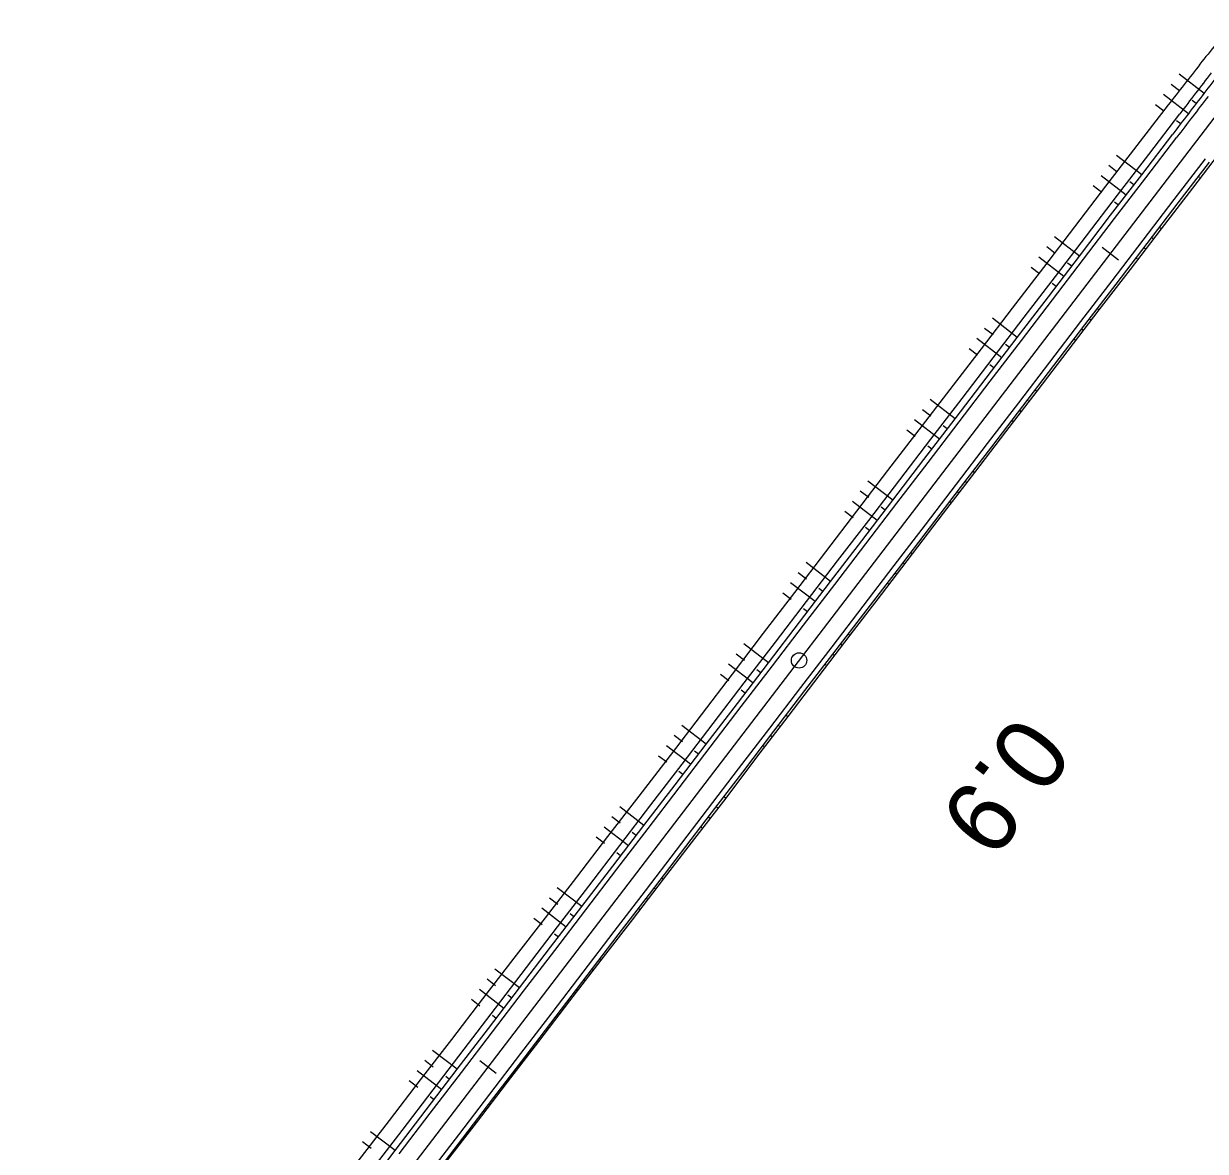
# Model space of a CAD drawing. Extents: x -481645 to -478728, y -1113199 to -1110710.
# Drawn here: x -479367.1 to -479251.7, y -1111179 to -1111068.9 of the extents above; entities that cross this region are included whole.
import ezdxf

# ---------------------------------------------------------------- set-up
doc = ezdxf.new("R2010")
doc.units = 0
for name, color, linetype in [('CP14_HATCH_SLOPE_L', 7, 'Continuous'), ('CP1_HECTOMETRY', 7, 'Continuous'), ('O6_HATCH_SLOPE_L', 7, 'Continuous'), ('O6_HATCH_SLOPE_R', 7, 'Continuous'), ('O6_HLBODY', 7, 'Continuous'), ('O6_HRANA_TELESO', 7, 'Continuous'), ('O6_OSA', 7, 'Continuous'), ('O6_VOZOVKA', 7, 'Continuous'), ('O6_ZPEVKRAJ', 7, 'Continuous')]:
    doc.layers.add(name, color=color, linetype=linetype)

msp = doc.modelspace()

# ---------------------------------------------------------------- linework, layer by layer
at = {"layer": 'CP14_HATCH_SLOPE_L'}
for p, q in [((-479252.35, -1111083.82), (-479252.25, -1111083.89)), ((-479252.15, -1111083.97), (-479252.15, -1111083.97)), ((-479256.15, -1111088.78), (-479255.95, -1111088.93)), ((-479256.91, -1111089.77), (-479256.81, -1111089.85)), ((-479256.71, -1111089.92), (-479256.71, -1111089.92)), ((-479257.67, -1111090.76), (-479257.47, -1111090.91)), ((-479258.43, -1111091.76), (-479258.33, -1111091.83)), ((-479258.23, -1111091.91), (-479258.23, -1111091.91)), ((-479262.23, -1111096.72), (-479262.04, -1111096.86)), ((-479262.99, -1111097.71), (-479262.89, -1111097.78)), ((-479262.8, -1111097.86), (-479262.8, -1111097.86)), ((-479263.75, -1111098.71), (-479263.56, -1111098.85)), ((-479264.51, -1111099.7), (-479264.41, -1111099.77)), ((-479264.32, -1111099.84), (-479264.32, -1111099.84)), ((-479268.3, -1111104.66), (-479268.12, -1111104.8)), ((-479269.07, -1111105.65), (-479268.98, -1111105.72)), ((-479268.89, -1111105.79), (-479268.89, -1111105.79)), ((-479269.83, -1111106.65), (-479269.65, -1111106.78)), ((-479270.58, -1111107.64), (-479270.49, -1111107.71)), ((-479270.41, -1111107.77), (-479270.41, -1111107.77)), ((-479274.38, -1111112.6), (-479274.21, -1111112.73)), ((-479275.14, -1111113.59), (-479275.06, -1111113.66)), ((-479274.97, -1111113.72), (-479274.97, -1111113.72)), ((-479275.9, -1111114.59), (-479275.73, -1111114.72)), ((-479276.66, -1111115.58), (-479276.58, -1111115.64)), ((-479276.49, -1111115.71), (-479276.49, -1111115.71)), ((-479280.46, -1111120.54), (-479280.29, -1111120.67)), ((-479281.22, -1111121.53), (-479281.14, -1111121.6)), ((-479281.05, -1111121.66), (-479281.05, -1111121.66)), ((-479282.74, -1111123.52), (-479282.66, -1111123.58)), ((-479281.98, -1111122.53), (-479281.81, -1111122.66)), ((-479282.57, -1111123.65), (-479282.57, -1111123.65)), ((-479286.54, -1111128.48), (-479286.37, -1111128.61)), ((-479288.06, -1111130.47), (-479287.89, -1111130.6)), ((-479287.3, -1111129.47), (-479287.22, -1111129.54)), ((-479287.13, -1111129.6), (-479287.13, -1111129.6)), ((-479288.82, -1111131.46), (-479288.74, -1111131.52)), ((-479288.65, -1111131.59), (-479288.65, -1111131.59)), ((-479293.38, -1111137.42), (-479293.3, -1111137.48)), ((-479292.62, -1111136.42), (-479292.45, -1111136.55)), ((-479294.14, -1111138.41), (-479293.97, -1111138.53)), ((-479293.21, -1111137.54), (-479293.21, -1111137.54)), ((-479294.9, -1111139.4), (-479294.82, -1111139.46)), ((-479294.73, -1111139.53), (-479294.73, -1111139.53)), ((-479298.7, -1111144.36), (-479298.49, -1111144.52)), ((-479299.46, -1111145.36), (-479299.35, -1111145.43)), ((-479299.25, -1111145.51), (-479299.25, -1111145.51)), ((-479300.22, -1111146.35), (-479300.02, -1111146.5)), ((-479300.98, -1111147.34), (-479300.88, -1111147.42)), ((-479300.78, -1111147.49), (-479300.78, -1111147.49)), ((-479304.78, -1111152.3), (-479304.6, -1111152.44)), ((-479305.54, -1111153.3), (-479305.45, -1111153.36)), ((-479305.36, -1111153.43), (-479305.36, -1111153.43)), ((-479306.29, -1111154.29), (-479306.12, -1111154.42)), ((-479307.05, -1111155.28), (-479306.97, -1111155.35)), ((-479306.89, -1111155.41), (-479306.89, -1111155.41)), ((-479310.85, -1111160.24), (-479310.7, -1111160.36)), ((-479311.61, -1111161.24), (-479311.54, -1111161.29)), ((-479311.46, -1111161.35), (-479311.46, -1111161.35)), ((-479312.37, -1111162.23), (-479312.22, -1111162.34)), ((-479313.13, -1111163.22), (-479313.06, -1111163.28)), ((-479312.99, -1111163.33), (-479312.99, -1111163.33)), ((-479316.93, -1111168.19), (-479316.8, -1111168.29)), ((-479317.69, -1111169.18), (-479317.62, -1111169.23)), ((-479317.56, -1111169.28), (-479317.56, -1111169.28)), ((-479318.45, -1111170.17), (-479318.32, -1111170.27)), ((-479319.21, -1111171.16), (-479319.15, -1111171.21)), ((-479319.08, -1111171.26), (-479319.08, -1111171.26)), ((-479323.01, -1111176.13), (-479322.89, -1111176.22)), ((-479323.77, -1111177.12), (-479323.71, -1111177.16)), ((-479323.65, -1111177.21), (-479323.65, -1111177.21)), ((-479324.53, -1111178.11), (-479324.42, -1111178.2))]:
    msp.add_line(p, q, dxfattribs=at)
at = {"layer": 'CP1_HECTOMETRY'}
msp.add_line((-479472.65, -1111367.92), (-479250.4, -1111077.57), dxfattribs=at)
at = {"layer": 'O6_HATCH_SLOPE_L'}
msp.add_circle((-479291.37, -1111131.08), 0.75, dxfattribs=at)
at = {"layer": 'O6_HATCH_SLOPE_R'}
for p, q in [((-479251.81, -1111075.71), (-479254.25, -1111073.84)), ((-479254.2, -1111075.46), (-479255.02, -1111074.83)), ((-479253.33, -1111077.7), (-479255.78, -1111075.83)), ((-479255.72, -1111077.45), (-479256.54, -1111076.82)), ((-479252.58, -1111076.71), (-479252.98, -1111076.4)), ((-479254.09, -1111078.69), (-479254.49, -1111078.39)), ((-479257.89, -1111083.66), (-479260.35, -1111081.77)), ((-479260.28, -1111083.4), (-479261.11, -1111082.77)), ((-479259.41, -1111085.64), (-479261.87, -1111083.76)), ((-479258.65, -1111084.65), (-479259.05, -1111084.34)), ((-479261.8, -1111085.39), (-479262.63, -1111084.75)), ((-479260.17, -1111086.63), (-479260.57, -1111086.33)), ((-479263.97, -1111091.6), (-479266.42, -1111089.72)), ((-479266.35, -1111091.35), (-479267.18, -1111090.71)), ((-479265.49, -1111093.58), (-479267.94, -1111091.71)), ((-479264.73, -1111092.59), (-479265.13, -1111092.28)), ((-479267.87, -1111093.33), (-479268.7, -1111092.7)), ((-479266.25, -1111094.57), (-479266.65, -1111094.27)), ((-479270.05, -1111099.54), (-479272.48, -1111097.67)), ((-479272.42, -1111099.29), (-479273.24, -1111098.67)), ((-479271.57, -1111101.52), (-479274, -1111099.66)), ((-479270.81, -1111100.53), (-479271.2, -1111100.23)), ((-479273.94, -1111101.28), (-479274.76, -1111100.65)), ((-479272.33, -1111102.51), (-479272.72, -1111102.21)), ((-479276.13, -1111107.48), (-479278.57, -1111105.61)), ((-479278.5, -1111107.24), (-479279.32, -1111106.6)), ((-479280.02, -1111109.22), (-479280.84, -1111108.59)), ((-479277.65, -1111109.46), (-479280.08, -1111107.6)), ((-479276.89, -1111108.47), (-479277.28, -1111108.17)), ((-479278.41, -1111110.46), (-479278.8, -1111110.15)), ((-479282.21, -1111115.42), (-479284.64, -1111113.56)), ((-479284.57, -1111115.18), (-479285.4, -1111114.55)), ((-479286.09, -1111117.17), (-479286.91, -1111116.54)), ((-479283.73, -1111117.4), (-479286.15, -1111115.55)), ((-479282.97, -1111116.41), (-479283.36, -1111116.11)), ((-479284.49, -1111118.4), (-479284.88, -1111118.1)), ((-479288.29, -1111123.36), (-479290.69, -1111121.52)), ((-479289.8, -1111125.34), (-479292.21, -1111123.5)), ((-479290.64, -1111123.13), (-479291.45, -1111122.51)), ((-479292.15, -1111125.12), (-479292.97, -1111124.5)), ((-479289.04, -1111124.35), (-479289.43, -1111124.05)), ((-479290.56, -1111126.34), (-479290.95, -1111126.04)), ((-479296.71, -1111131.08), (-479297.52, -1111130.46)), ((-479294.36, -1111131.3), (-479296.76, -1111129.46)), ((-479295.88, -1111133.28), (-479298.27, -1111131.45)), ((-479298.22, -1111133.07), (-479299.03, -1111132.45)), ((-479295.12, -1111132.29), (-479295.51, -1111132)), ((-479296.64, -1111134.28), (-479297.03, -1111133.98)), ((-479300.44, -1111139.24), (-479302.81, -1111137.43)), ((-479302.77, -1111139.03), (-479303.57, -1111138.42)), ((-479301.96, -1111141.22), (-479304.33, -1111139.41)), ((-479304.29, -1111141.02), (-479305.09, -1111140.41)), ((-479301.2, -1111140.23), (-479301.59, -1111139.94)), ((-479302.72, -1111142.22), (-479303.1, -1111141.92)), ((-479306.52, -1111147.18), (-479308.89, -1111145.36)), ((-479308.85, -1111146.97), (-479309.65, -1111146.35)), ((-479308.04, -1111149.17), (-479310.42, -1111147.35)), ((-479310.37, -1111148.96), (-479311.18, -1111148.34)), ((-479307.28, -1111148.17), (-479307.66, -1111147.88)), ((-479308.8, -1111150.16), (-479309.18, -1111149.87)), ((-479312.6, -1111155.12), (-479314.99, -1111153.29)), ((-479314.93, -1111154.91), (-479315.75, -1111154.28)), ((-479314.12, -1111157.11), (-479316.51, -1111155.27)), ((-479313.36, -1111156.11), (-479313.74, -1111155.82)), ((-479316.45, -1111156.89), (-479317.27, -1111156.27)), ((-479314.88, -1111158.1), (-479315.26, -1111157.81)), ((-479318.68, -1111163.06), (-479321.08, -1111161.22)), ((-479321.02, -1111162.84), (-479321.84, -1111162.21)), ((-479320.2, -1111165.05), (-479322.6, -1111163.2)), ((-479319.44, -1111164.05), (-479319.82, -1111163.76)), ((-479322.54, -1111164.83), (-479323.36, -1111164.2)), ((-479320.96, -1111166.04), (-479321.33, -1111165.75)), ((-479324.76, -1111171), (-479327.17, -1111169.15)), ((-479327.1, -1111170.78), (-479327.93, -1111170.14)), ((-479326.28, -1111172.99), (-479328.69, -1111171.14)), ((-479325.52, -1111171.99), (-479325.89, -1111171.71)), ((-479328.62, -1111172.77), (-479329.45, -1111172.13)), ((-479327.03, -1111173.98), (-479327.41, -1111173.69)), ((-479330.83, -1111178.94), (-479333.24, -1111177.1)), ((-479333.17, -1111178.73), (-479334.01, -1111178.09))]:
    msp.add_line(p, q, dxfattribs=at)
at = {"layer": 'O6_HLBODY'}
for p, q in [((-479260.18, -1111091.99), (-479261.77, -1111090.77)), ((-479320.96, -1111171.4), (-479322.55, -1111170.18))]:
    msp.add_line(p, q, dxfattribs=at)
at = {"layer": 'O6_HRANA_TELESO'}
for p, q in [((-479257.21, -1111081.67), (-479254.17, -1111077.7)), ((-479260.25, -1111085.64), (-479257.21, -1111081.67)), ((-479263.29, -1111089.61), (-479260.25, -1111085.64)), ((-479266.33, -1111093.58), (-479263.29, -1111089.61)), ((-479269.37, -1111097.55), (-479266.33, -1111093.58)), ((-479272.41, -1111101.52), (-479269.37, -1111097.55)), ((-479275.45, -1111105.49), (-479272.41, -1111101.52)), ((-479278.49, -1111109.46), (-479275.45, -1111105.49)), ((-479281.53, -1111113.43), (-479278.49, -1111109.46)), ((-479284.56, -1111117.4), (-479281.53, -1111113.43)), ((-479287.6, -1111121.37), (-479284.56, -1111117.4)), ((-479290.64, -1111125.34), (-479287.6, -1111121.37)), ((-479293.68, -1111129.31), (-479290.64, -1111125.34)), ((-479296.72, -1111133.28), (-479293.68, -1111129.31)), ((-479299.76, -1111137.25), (-479296.72, -1111133.28)), ((-479302.8, -1111141.22), (-479299.76, -1111137.25)), ((-479305.84, -1111145.19), (-479302.8, -1111141.22)), ((-479308.88, -1111149.16), (-479305.84, -1111145.19)), ((-479311.92, -1111153.13), (-479308.88, -1111149.16)), ((-479314.96, -1111157.1), (-479311.92, -1111153.13)), ((-479317.99, -1111161.07), (-479314.96, -1111157.1)), ((-479321.03, -1111165.04), (-479317.99, -1111161.07)), ((-479324.07, -1111169.02), (-479321.03, -1111165.04)), ((-479327.11, -1111172.99), (-479324.07, -1111169.02)), ((-479330.15, -1111176.96), (-479327.11, -1111172.99)), ((-479333.19, -1111180.93), (-479330.15, -1111176.96))]:
    msp.add_line(p, q, dxfattribs=at)
msp.add_arc((-478532.29, -1111629.71), 908.75, 142.27851, 142.59535, dxfattribs=at)
at = {"layer": 'O6_OSA'}
for p, q in [((-479258.35, -1111080.8), (-479255.29, -1111076.84)), ((-479261.39, -1111084.76), (-479258.35, -1111080.8)), ((-479252.91, -1111084.96), (-479249.86, -1111081)), ((-479264.44, -1111088.73), (-479261.39, -1111084.76)), ((-479255.95, -1111088.93), (-479252.91, -1111084.96)), ((-479267.47, -1111092.7), (-479264.44, -1111088.73)), ((-479258.99, -1111092.9), (-479255.95, -1111088.93)), ((-479270.51, -1111096.68), (-479267.47, -1111092.7)), ((-479262.04, -1111096.86), (-479258.99, -1111092.9)), ((-479273.55, -1111100.64), (-479270.51, -1111096.68)), ((-479265.08, -1111100.83), (-479262.04, -1111096.86)), ((-479276.6, -1111104.61), (-479273.55, -1111100.64)), ((-479268.12, -1111104.8), (-479265.08, -1111100.83)), ((-479279.65, -1111108.57), (-479276.6, -1111104.61)), ((-479271.17, -1111108.77), (-479268.12, -1111104.8)), ((-479282.69, -1111112.54), (-479279.65, -1111108.57)), ((-479274.21, -1111112.73), (-479271.17, -1111108.77)), ((-479285.72, -1111116.51), (-479282.69, -1111112.54)), ((-479277.26, -1111116.7), (-479274.21, -1111112.73)), ((-479288.76, -1111120.49), (-479285.72, -1111116.51)), ((-479280.29, -1111120.67), (-479277.26, -1111116.7)), ((-479291.79, -1111124.46), (-479288.76, -1111120.49)), ((-479283.33, -1111124.64), (-479280.29, -1111120.67)), ((-479294.83, -1111128.43), (-479291.79, -1111124.46)), ((-479286.37, -1111128.61), (-479283.33, -1111124.64)), ((-479297.87, -1111132.41), (-479294.83, -1111128.43)), ((-479289.42, -1111132.58), (-479286.37, -1111128.61)), ((-479300.9, -1111136.38), (-479297.87, -1111132.41)), ((-479292.45, -1111136.55), (-479289.42, -1111132.58)), ((-479303.93, -1111140.36), (-479300.9, -1111136.38)), ((-479295.49, -1111140.52), (-479292.45, -1111136.55)), ((-479306.98, -1111144.32), (-479303.93, -1111140.36)), ((-479298.49, -1111144.52), (-479295.49, -1111140.52)), ((-479310.04, -1111148.28), (-479306.98, -1111144.32)), ((-479301.54, -1111148.48), (-479298.49, -1111144.52)), ((-479313.09, -1111152.24), (-479310.04, -1111148.28)), ((-479304.6, -1111152.44), (-479301.54, -1111148.48)), ((-479316.14, -1111156.2), (-479313.09, -1111152.24)), ((-479307.65, -1111156.4), (-479304.6, -1111152.44)), ((-479319.19, -1111160.16), (-479316.14, -1111156.2)), ((-479310.7, -1111160.36), (-479307.65, -1111156.4)), ((-479322.25, -1111164.12), (-479319.19, -1111160.16)), ((-479313.75, -1111164.32), (-479310.7, -1111160.36)), ((-479325.3, -1111168.08), (-479322.25, -1111164.12)), ((-479316.8, -1111168.29), (-479313.75, -1111164.32)), ((-479328.35, -1111172.04), (-479325.3, -1111168.08)), ((-479319.84, -1111172.25), (-479316.8, -1111168.29)), ((-479331.39, -1111176.01), (-479328.35, -1111172.04)), ((-479322.89, -1111176.22), (-479319.84, -1111172.25)), ((-479334.44, -1111179.97), (-479331.39, -1111176.01)), ((-479325.94, -1111180.18), (-479322.89, -1111176.22))]:
    msp.add_line(p, q, dxfattribs=at)
for centre, radius, start, end in [((-479013.18, -1111261.17), 304.29, 140.814, 141.769), ((-478533.23, -1111635.43), 912.91, 141.95827, 142.27443)]:
    msp.add_arc(centre, radius, start, end, dxfattribs=at)
at = {"layer": 'O6_VOZOVKA'}
for p, q in [((-479257.5, -1111083.96), (-479254.46, -1111079.99)), ((-479254.72, -1111086.09), (-479251.68, -1111082.12)), ((-479260.54, -1111087.93), (-479257.5, -1111083.96)), ((-479257.76, -1111090.06), (-479254.72, -1111086.09)), ((-479263.57, -1111091.9), (-479260.54, -1111087.93)), ((-479260.79, -1111094.03), (-479257.76, -1111090.06)), ((-479266.61, -1111095.87), (-479263.57, -1111091.9)), ((-479263.83, -1111098), (-479260.79, -1111094.03)), ((-479269.65, -1111099.84), (-479266.61, -1111095.87)), ((-479266.87, -1111101.97), (-479263.83, -1111098)), ((-479272.69, -1111103.81), (-479269.65, -1111099.84)), ((-479269.91, -1111105.94), (-479266.87, -1111101.97)), ((-479275.73, -1111107.78), (-479272.69, -1111103.81)), ((-479272.95, -1111109.91), (-479269.91, -1111105.94)), ((-479278.77, -1111111.75), (-479275.73, -1111107.78)), ((-479275.99, -1111113.88), (-479272.95, -1111109.91)), ((-479281.81, -1111115.72), (-479278.77, -1111111.75)), ((-479279.03, -1111117.85), (-479275.99, -1111113.88)), ((-479284.85, -1111119.69), (-479281.81, -1111115.72)), ((-479282.07, -1111121.82), (-479279.03, -1111117.85)), ((-479287.89, -1111123.66), (-479284.85, -1111119.69)), ((-479285.11, -1111125.79), (-479282.07, -1111121.82)), ((-479290.93, -1111127.63), (-479287.89, -1111123.66)), ((-479288.15, -1111129.76), (-479285.11, -1111125.79)), ((-479293.97, -1111131.6), (-479290.93, -1111127.63)), ((-479291.19, -1111133.73), (-479288.15, -1111129.76)), ((-479297.01, -1111135.57), (-479293.97, -1111131.6)), ((-479294.23, -1111137.7), (-479291.19, -1111133.73)), ((-479300.04, -1111139.54), (-479297.01, -1111135.57)), ((-479297.27, -1111141.67), (-479294.23, -1111137.7)), ((-479303.08, -1111143.51), (-479300.04, -1111139.54)), ((-479300.3, -1111145.64), (-479297.27, -1111141.67)), ((-479306.12, -1111147.48), (-479303.08, -1111143.51)), ((-479303.34, -1111149.61), (-479300.3, -1111145.64)), ((-479309.16, -1111151.45), (-479306.12, -1111147.48)), ((-479306.38, -1111153.58), (-479303.34, -1111149.61)), ((-479312.2, -1111155.43), (-479309.16, -1111151.45)), ((-479309.42, -1111157.55), (-479306.38, -1111153.58)), ((-479315.24, -1111159.4), (-479312.2, -1111155.43)), ((-479312.46, -1111161.52), (-479309.42, -1111157.55)), ((-479318.28, -1111163.36), (-479315.24, -1111159.4)), ((-479315.5, -1111165.49), (-479312.46, -1111161.52)), ((-479321.32, -1111167.33), (-479318.28, -1111163.36)), ((-479318.54, -1111169.46), (-479315.5, -1111165.49)), ((-479324.36, -1111171.31), (-479321.32, -1111167.33)), ((-479321.58, -1111173.43), (-479318.54, -1111169.46)), ((-479327.4, -1111175.28), (-479324.36, -1111171.31)), ((-479324.62, -1111177.4), (-479321.58, -1111173.43)), ((-479330.44, -1111179.25), (-479327.4, -1111175.28)), ((-479327.66, -1111181.37), (-479324.62, -1111177.4))]:
    msp.add_line(p, q, dxfattribs=at)
msp.add_arc((-478534.18, -1111628.33), 905.25, 142.40137, 142.71806, dxfattribs=at)
at = {"layer": 'O6_ZPEVKRAJ'}
for p, q in [((-479257.89, -1111083.66), (-479254.85, -1111079.69)), ((-479254.32, -1111086.39), (-479251.28, -1111082.42)), ((-479260.93, -1111087.62), (-479257.89, -1111083.66)), ((-479257.36, -1111090.36), (-479254.32, -1111086.39)), ((-479263.97, -1111091.6), (-479260.93, -1111087.62)), ((-479260.4, -1111094.33), (-479257.36, -1111090.36)), ((-479267.01, -1111095.57), (-479263.97, -1111091.6)), ((-479263.44, -1111098.3), (-479260.4, -1111094.33)), ((-479270.05, -1111099.54), (-479267.01, -1111095.57)), ((-479266.48, -1111102.27), (-479263.44, -1111098.3)), ((-479273.09, -1111103.51), (-479270.05, -1111099.54)), ((-479269.52, -1111106.24), (-479266.48, -1111102.27)), ((-479276.13, -1111107.48), (-479273.09, -1111103.51)), ((-479272.55, -1111110.21), (-479269.52, -1111106.24)), ((-479279.17, -1111111.45), (-479276.13, -1111107.48)), ((-479275.59, -1111114.18), (-479272.55, -1111110.21)), ((-479282.21, -1111115.42), (-479279.17, -1111111.45)), ((-479278.63, -1111118.15), (-479275.59, -1111114.18)), ((-479285.25, -1111119.39), (-479282.21, -1111115.42)), ((-479281.67, -1111122.12), (-479278.63, -1111118.15)), ((-479288.29, -1111123.36), (-479285.25, -1111119.39)), ((-479284.71, -1111126.09), (-479281.67, -1111122.12)), ((-479291.32, -1111127.33), (-479288.29, -1111123.36)), ((-479287.75, -1111130.06), (-479284.71, -1111126.09)), ((-479294.36, -1111131.3), (-479291.32, -1111127.33)), ((-479290.79, -1111134.03), (-479287.75, -1111130.06)), ((-479297.4, -1111135.27), (-479294.36, -1111131.3)), ((-479293.83, -1111138), (-479290.79, -1111134.03)), ((-479300.44, -1111139.24), (-479297.4, -1111135.27)), ((-479296.87, -1111141.98), (-479293.83, -1111138)), ((-479303.48, -1111143.21), (-479300.44, -1111139.24)), ((-479299.91, -1111145.95), (-479296.87, -1111141.98)), ((-479306.52, -1111147.18), (-479303.48, -1111143.21)), ((-479302.95, -1111149.92), (-479299.91, -1111145.95)), ((-479309.56, -1111151.15), (-479306.52, -1111147.18)), ((-479305.99, -1111153.89), (-479302.95, -1111149.92)), ((-479312.6, -1111155.12), (-479309.56, -1111151.15)), ((-479309.03, -1111157.86), (-479305.99, -1111153.89)), ((-479315.64, -1111159.09), (-479312.6, -1111155.12)), ((-479312.06, -1111161.83), (-479309.03, -1111157.86)), ((-479318.68, -1111163.06), (-479315.64, -1111159.09)), ((-479315.1, -1111165.8), (-479312.06, -1111161.83)), ((-479321.72, -1111167.03), (-479318.68, -1111163.06)), ((-479318.14, -1111169.77), (-479315.1, -1111165.8)), ((-479324.76, -1111171), (-479321.72, -1111167.03)), ((-479321.18, -1111173.74), (-479318.14, -1111169.77)), ((-479327.79, -1111174.97), (-479324.76, -1111171)), ((-479324.22, -1111177.71), (-479321.18, -1111173.74)), ((-479330.83, -1111178.94), (-479327.79, -1111174.97)), ((-479327.26, -1111181.68), (-479324.22, -1111177.71)), ((-479333.87, -1111182.91), (-479330.83, -1111178.94))]:
    msp.add_line(p, q, dxfattribs=at)
for centre, radius, start, end in [((-479012.18, -1111259.92), 302.25, 141.4954, 142.4503), ((-478533.39, -1111628.94), 906.75, 142.40159, 142.71782)]:
    msp.add_arc(centre, radius, start, end, dxfattribs=at)

# ---------------------------------------------------------------- texts
at = {"layer": 'O6_HATCH_SLOPE_L'}
msp.add_text('0.9', height=7, rotation=232.5212, dxfattribs=at).set_placement((-479269.98, -1111136.07))

doc.saveas('drawing.dxf')
